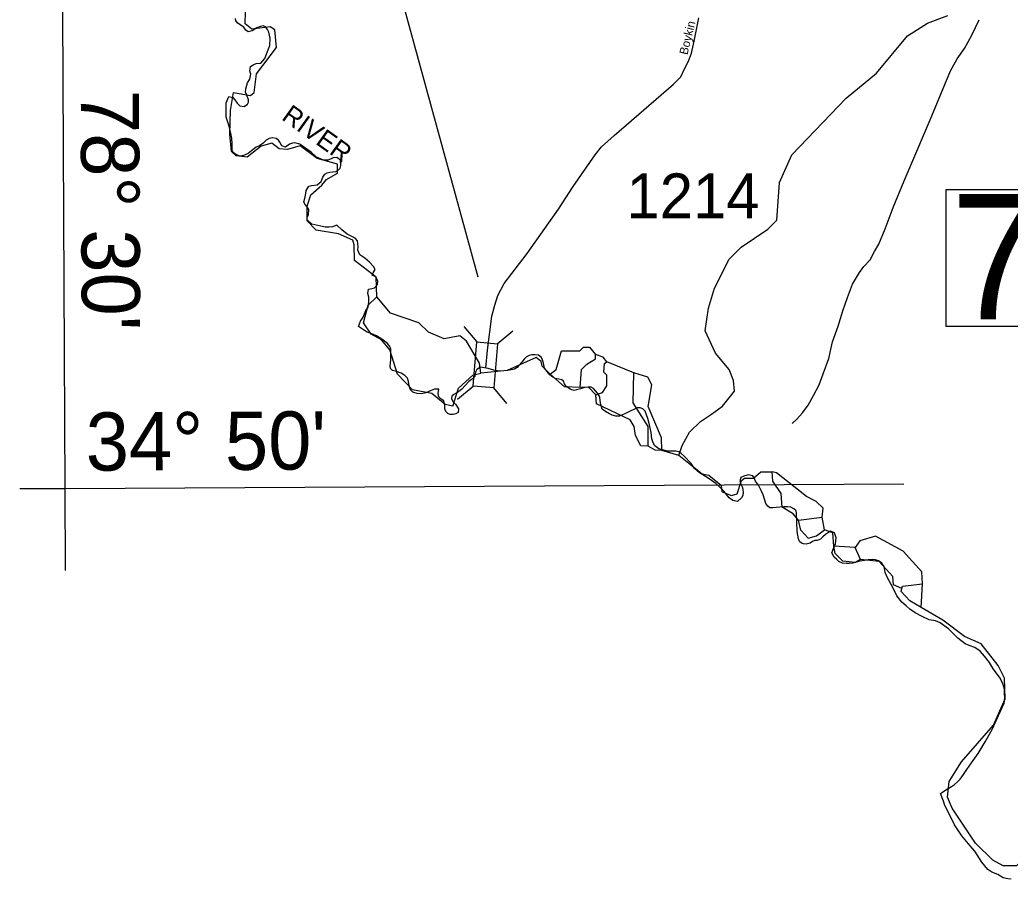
# Model space of a CAD drawing. Extents: x 2093524 to 2270757, y 289120 to 570408.
# Drawn here: x 2149570 to 2160640, y 390085 to 399685 of the extents above; entities that cross this region are included whole.
import ezdxf

# ---------------------------------------------------------------- set-up
doc = ezdxf.new("R2010")
doc.units = 0
for name, color, linetype in [('Exist Boundary Political CountyLine', 7, 'Continuous'), ('Exist Hydrographic Misc Water Feature', 7, 'Continuous'), ('Exist Hydrographic River Shore Label', 7, 'Continuous'), ('Exist Road Non-System Type 51', 7, 'Continuous'), ('Exist Road Secondary Structure Standard Bridge CELL', 7, 'Continuous'), ('Exist Road Secondary Structure Standard Bridge Number Label', 7, 'Continuous'), ('Exist Road Secondary Type 51 Attributed', 7, 'Continuous'), ('Exist Road Secondary Type 51 Label', 7, 'Continuous'), ('Exist Road Secondary Type 51 Number Label', 7, 'Continuous'), ('Map Preparation Longitude Latitude Label', 7, 'Continuous'), ('Map Preparation Longitude Latitude Lines', 7, 'Continuous')]:
    doc.layers.add(name, color=color, linetype=linetype)

msp = doc.modelspace()

# ---------------------------------------------------------------- linework, layer by layer
at = {"layer": 'Exist Boundary Political CountyLine'}
for points in [[(2153159, 398059), (2153154, 398118), (2153112, 398147), (2153074, 398143), (2153018, 398116), (2152965, 398116), (2152886, 398151), (2152826, 398205), (2152742, 398265), (2152700, 398296), (2152644, 398309), (2152616, 398308), (2152585, 398295), (2152538, 398264), (2152500, 398279), (2152476, 398320), (2152462, 398342), (2152437, 398358), (2152396, 398366), (2152358, 398358), (2152322, 398342), (2152289, 398308), (2152248, 398277), (2152210, 398261), (2152160, 398220), (2152121, 398193), (2152070, 398168), (2152032, 398163), (2151984, 398179), (2151956, 398203), (2151945, 398230), (2151943, 398303), (2151941, 398358), (2151930, 398418), (2151906, 398508), (2151876, 398598), (2151876, 398659), (2151876, 398759), (2151906, 398827), (2151952, 398816), (2151974, 398790), (2152000, 398753), (2152030, 398724), (2152076, 398716), (2152115, 398741), (2152126, 398766), (2152125, 398792), (2152106, 398843), (2152093, 398878), (2152096, 398915), (2152116, 398981), (2152141, 399021), (2152152, 399077), (2152142, 399111), (2152148, 399163), (2152184, 399184), (2152213, 399198), (2152263, 399199), (2152310, 399251), (2152328, 399300), (2152348, 399362), (2152363, 399398), (2152368, 399480), (2152354, 399546), (2152339, 399577), (2152315, 399605), (2152290, 399616), (2152260, 399611), (2152219, 399596), (2152167, 399560), (2152122, 399552), (2152095, 399570), (2152075, 399603), (2152032, 399630), (2152007, 399646), (2151986, 399673), (2151980, 399700)], [(2154420, 395500), (2154398, 395481), (2154395, 395454), (2154410, 395422), (2154441, 395390), (2154475, 395339), (2154468, 395297), (2154444, 395284), (2154415, 395277), (2154382, 395277), (2154354, 395287), (2154332, 395308), (2154319, 395341), (2154322, 395377), (2154310, 395429), (2154278, 395447), (2154254, 395472), (2154247, 395509), (2154255, 395559), (2154204, 395558), (2154166, 395546), (2154108, 395519), (2154058, 395507), (2154013, 395512), (2153961, 395524), (2153936, 395551), (2153921, 395598), (2153913, 395644), (2153903, 395681), (2153874, 395712), (2153833, 395738), (2153780, 395755), (2153734, 395767), (2153714, 395790), (2153709, 395817), (2153718, 395885), (2153718, 395967), (2153718, 396005), (2153706, 396036), (2153678, 396068), (2153618, 396118), (2153557, 396154), (2153503, 396177), (2153444, 396198), (2153355, 396259), (2153377, 396317), (2153408, 396362), (2153439, 396439), (2153463, 396474), (2153472, 396533), (2153472, 396586), (2153460, 396627), (2153468, 396675), (2153506, 396685), (2153535, 396691), (2153569, 396729), (2153571, 396767), (2153548, 396813), (2153509, 396832), (2153518, 396859), (2153543, 396896), (2153525, 396928), (2153478, 396978), (2153428, 397024), (2153372, 397058), (2153348, 397113), (2153352, 397150), (2153349, 397186), (2153343, 397215), (2153317, 397244), (2153229, 397290), (2153168, 397340), (2153112, 397390), (2153064, 397373), (2153028, 397368), (2152983, 397368), (2152933, 397380), (2152834, 397404), (2152780, 397452), (2152781, 397478), (2152795, 397509), (2152800, 397565), (2152782, 397594), (2152754, 397624), (2152746, 397653), (2152757, 397689), (2152768, 397744), (2152772, 397779), (2152799, 397828), (2152829, 397833), (2152894, 397840), (2152937, 397879), (2152956, 397929), (2152980, 397962), (2153004, 397977), (2153036, 397984), (2153101, 397990), (2153129, 398007), (2153150, 398029), (2153159, 398059)], [(2157877, 394379), (2157855, 394426), (2157828, 394487), (2157792, 394531), (2157777, 394567), (2157762, 394591), (2157710, 394603), (2157662, 394589), (2157630, 394574), (2157618, 394534), (2157630, 394499), (2157648, 394462), (2157651, 394436), (2157654, 394404), (2157650, 394373), (2157636, 394347), (2157593, 394306), (2157540, 394314), (2157497, 394347), (2157440, 394420), (2157396, 394465), (2157351, 394507), (2157254, 394571), (2157167, 394623), (2157112, 394674), (2157073, 394727), (2156995, 394810), (2156964, 394839), (2156936, 394860), (2156903, 394866), (2156846, 394866), (2156808, 394868), (2156768, 394878), (2156711, 394892), (2156667, 394926), (2156650, 394961), (2156636, 395004), (2156628, 395075), (2156605, 395177), (2156588, 395232), (2156560, 395312), (2156534, 395339), (2156503, 395351), (2156470, 395349), (2156434, 395333), (2156392, 395315), (2156340, 395288), (2156274, 395259), (2156232, 395259), (2156190, 395268), (2156163, 395283), (2156116, 395309), (2156081, 395335), (2156063, 395387), (2156058, 395430), (2156052, 395473), (2156027, 395516), (2155984, 395568), (2155956, 395581), (2155919, 395583), (2155884, 395576), (2155838, 395563), (2155794, 395550), (2155766, 395546), (2155728, 395555), (2155676, 395590), (2155658, 395620), (2155648, 395647), (2155629, 395665), (2155595, 395670), (2155552, 395678), (2155526, 395692), (2155495, 395720), (2155436, 395794), (2155422, 395848), (2155413, 395886), (2155401, 395914), (2155368, 395940), (2155327, 395943), (2155294, 395941), (2155264, 395937), (2155235, 395922), (2155206, 395895), (2155182, 395862), (2155149, 395824), (2155128, 395802), (2155098, 395781), (2155026, 395768), (2154932, 395762), (2154867, 395771), (2154806, 395790), (2154719, 395804), (2154678, 395778), (2154665, 395748), (2154657, 395703), (2154628, 395674), (2154588, 395643), (2154511, 395558), (2154474, 395528), (2154420, 395500)], [(2160562, 390102), (2160503, 390136), (2160436, 390162), (2160391, 390192), (2160323, 390277), (2160244, 390398), (2160194, 390458), (2160100, 390568), (2160019, 390693), (2159951, 390830), (2159909, 390910), (2159895, 390956), (2159860, 391042), (2159883, 391057), (2159922, 391084), (2159964, 391109), (2160014, 391140), (2160054, 391175), (2160082, 391202), (2160118, 391255), (2160157, 391309), (2160207, 391385), (2160281, 391491), (2160360, 391620), (2160439, 391758), (2160508, 391912), (2160574, 392050), (2160580, 392107), (2160578, 392159), (2160576, 392207), (2160558, 392270), (2160519, 392343), (2160450, 392434), (2160410, 392507), (2160351, 392578), (2160304, 392632), (2160246, 392673), (2160182, 392694), (2160136, 392714), (2160056, 392777), (2159949, 392883), (2159858, 392950), (2159806, 392970), (2159734, 392984), (2159656, 393018), (2159578, 393059), (2159518, 393100), (2159476, 393138), (2159430, 393180), (2159373, 393251), (2159327, 393344), (2159269, 393453), (2159241, 393512), (2159231, 393577), (2159206, 393616), (2159168, 393642), (2159133, 393653), (2159099, 393655), (2159054, 393654), (2159011, 393647), (2158959, 393638), (2158878, 393616), (2158840, 393611), (2158809, 393613), (2158765, 393616), (2158726, 393633), (2158702, 393656), (2158673, 393683), (2158648, 393730), (2158667, 393792), (2158689, 393833), (2158696, 393899), (2158678, 393954), (2158632, 393973), (2158575, 393934), (2158544, 393908), (2158518, 393885), (2158483, 393870), (2158456, 393867), (2158429, 393856), (2158403, 393840), (2158358, 393826), (2158331, 393830), (2158306, 393838), (2158286, 393857), (2158272, 393888), (2158260, 393968), (2158254, 394081), (2158250, 394173), (2158247, 394201), (2158220, 394224), (2158189, 394241), (2158150, 394244), (2158110, 394243), (2158025, 394236), (2157986, 394233), (2157954, 394234), (2157930, 394251), (2157909, 394281), (2157877, 394379)], [(2160651, 390085), (2160613, 390090), (2160562, 390102)]]:
    msp.add_lwpolyline(points, dxfattribs=at)
at = {"layer": 'Exist Hydrographic Misc Water Feature'}
for p, q in [((2152370, 399608), (2152162, 399582)), ((2151958, 398874), (2152149, 398841)), ((2152702, 398276), (2152561, 398236)), ((2156432, 395741), (2156131, 395865)), ((2155658, 395586), (2155499, 395727)), ((2155833, 395579), (2155658, 395586)), ((2155925, 395581), (2155833, 395579)), ((2156009, 395497), (2155925, 395581)), ((2156017, 395395), (2156009, 395497)), ((2156595, 394924), (2156512, 394926)), ((2156670, 394877), (2156595, 394924)), ((2156745, 394875), (2156670, 394877)), ((2156937, 394819), (2156745, 394875)), ((2157196, 394611), (2156937, 394819)), ((2157422, 394413), (2157523, 394371)), ((2158274, 394094), (2158540, 394128)), ((2158566, 393986), (2158540, 394128)), ((2158909, 393789), (2158667, 393804)), ((2158968, 393657), (2158909, 393789)), ((2158968, 393657), (2158910, 393622)), ((2159428, 393333), (2159336, 393374)), ((2159646, 393119), (2159661, 393384)), ((2159646, 393119), (2159520, 393193))]:
    msp.add_line(p, q, dxfattribs=at)
for points in [[(2152162, 399582), (2152087, 399640), (2152094, 399774), (2152375, 400142), (2152441, 400390), (2152432, 400518), (2152373, 400559)], [(2156937, 394819), (2156973, 394931), (2157056, 395079), (2157177, 395199), (2157302, 395278), (2157425, 395370), (2157558, 395538), (2157549, 395657), (2157498, 395779), (2157347, 395962), (2157229, 396211), (2157269, 396463), (2157335, 396688), (2157500, 397012), (2157632, 397147), (2157931, 397348), (2158030, 397448), (2158061, 397867), (2158201, 398176), (2158806, 398810), (2159146, 399089), (2159493, 399505), (2159717, 399648), (2159942, 399732)], [(2152149, 398841), (2152191, 398873), (2152215, 399083), (2152438, 399377), (2152420, 399574), (2152370, 399608)], [(2151919, 398406), (2151925, 398672), (2151958, 398874)], [(2152112, 398150), (2151987, 398165), (2151936, 398215), (2151919, 398406)], [(2152386, 398308), (2152269, 398274), (2152112, 398150)], [(2152561, 398236), (2152469, 398244), (2152386, 398308)], [(2153562, 396592), (2153552, 396809), (2153309, 396997), (2153308, 397171), (2153291, 397224), (2153133, 397296), (2152883, 397337), (2152782, 397438), (2152781, 397602), (2152822, 397729), (2152946, 397838), (2152996, 397902), (2153121, 397972), (2153120, 398071), (2152895, 398137), (2152702, 398276)], [(2153413, 396300), (2153462, 396499), (2153562, 396592)], [(2154724, 395739), (2154707, 395848), (2154564, 396097), (2154489, 396154), (2154314, 396121), (2154139, 396194), (2154030, 396301), (2153712, 396409), (2153562, 396592)], [(2154410, 395371), (2154326, 395386), (2154176, 395511), (2153959, 395551), (2153791, 395725), (2153706, 395999), (2153614, 396109), (2153497, 396174), (2153413, 396300)], [(2155499, 395727), (2155565, 395778), (2155623, 395987), (2155831, 395986), (2155872, 396028), (2155939, 396030), (2156006, 395946)], [(2155340, 395911), (2155016, 395766), (2154724, 395739)], [(2155499, 395727), (2155407, 395817), (2155398, 395867), (2155340, 395911)], [(2155833, 395579), (2155849, 395779), (2155907, 395837), (2156006, 395897), (2156006, 395946)], [(2156131, 395865), (2156090, 395915), (2156006, 395946)], [(2156009, 395497), (2156083, 395522), (2156133, 395596), (2156132, 395714), (2156099, 395748), (2156107, 395846), (2156131, 395865)], [(2154410, 395371), (2154475, 395570), (2154633, 395715), (2154724, 395739)], [(2156595, 394924), (2156594, 395141), (2156425, 395407), (2156432, 395741)], [(2156745, 394875), (2156744, 395017), (2156592, 395367), (2156633, 395609), (2156591, 395692), (2156432, 395741)], [(2156512, 394926), (2156453, 395042), (2156435, 395141), (2156393, 395217), (2156017, 395395)], [(2157422, 394413), (2157414, 394478), (2157271, 394596), (2157196, 394611)], [(2157523, 394371), (2157589, 394390), (2157638, 394540), (2157671, 394565), (2157772, 394566)], [(2157772, 394566), (2157854, 394634), (2157979, 394634)], [(2158540, 394128), (2158548, 394229), (2158473, 394303), (2158364, 394361), (2158029, 394624), (2157979, 394634)], [(2158274, 394094), (2158215, 394167), (2158090, 394242), (2158081, 394393), (2157988, 394533), (2157979, 394634)], [(2158383, 393895), (2158300, 393985), (2158274, 394094)], [(2158383, 393895), (2158475, 393919), (2158566, 393986)], [(2158667, 393804), (2158658, 393955), (2158566, 393986)], [(2159661, 393384), (2159652, 393519), (2159442, 393749), (2159133, 393916), (2158958, 393864), (2158909, 393789)], [(2158910, 393622), (2158768, 393638), (2158684, 393722), (2158667, 393804)], [(2159336, 393374), (2159327, 393466), (2159176, 393633), (2158968, 393657)], [(2159520, 393193), (2159420, 393300), (2159428, 393333)], [(2159428, 393333), (2159436, 393359), (2159661, 393384)], [(2160562, 390233), (2160445, 390298), (2160252, 390489), (2159991, 390878), (2159941, 391003), (2159956, 391177), (2160097, 391397), (2160453, 391807), (2160584, 392099), (2160575, 392332), (2160507, 392472), (2160314, 392715), (2160131, 392797), (2159888, 392979), (2159646, 393119)], [(2161317, 390779), (2161208, 390768), (2161009, 390710), (2160918, 390600), (2160827, 390349), (2160711, 390234), (2160562, 390233)]]:
    msp.add_lwpolyline(points, dxfattribs=at)
at = {"layer": 'Exist Road Non-System Type 51'}
msp.add_lwpolyline([(2158204, 395174), (2158254, 395224), (2158319, 395294), (2158381, 395382), (2158440, 395489), (2158503, 395607), (2158549, 395731), (2158612, 395900), (2158655, 396088), (2158718, 396262), (2158769, 396434), (2158822, 396584), (2158879, 396733), (2158954, 396861), (2159004, 396931), (2159074, 397002), (2159125, 397096), (2159170, 397178), (2159241, 397351), (2159332, 397587), (2159454, 397886), (2159596, 398218), (2159744, 398569), (2159908, 398964), (2159973, 399114), (2160048, 399248), (2160130, 399363), (2160213, 399515), (2160294, 399686)], dxfattribs=at)
at = {"layer": 'Exist Road Secondary Structure Standard Bridge CELL'}
for p, q in [((2154681, 396087), (2154536, 396260)), ((2154907, 396067), (2155080, 396212)), ((2154463, 395448), (2154636, 395593)), ((2155012, 395399), (2154867, 395573))]:
    msp.add_line(p, q, dxfattribs=at)
msp.add_lwpolyline([(2154636, 395593), (2154680, 396087), (2154911, 396066), (2154867, 395573)], close=True, dxfattribs=at)
at = {"layer": 'Exist Road Secondary Structure Standard Bridge Number Label'}
msp.add_line((2154692, 396811), (2152660, 404215), dxfattribs=at)
msp.add_lwpolyline([(2159924, 397788), (2162501, 397788), (2162501, 396259), (2159924, 396259)], close=True, dxfattribs=at)
at = {"layer": 'Exist Road Secondary Type 51 Attributed'}
msp.add_lwpolyline([(2154778, 395795), (2154796, 395993), (2154846, 396375), (2154880, 396496), (2154914, 396606), (2154984, 396740), (2155242, 397076), (2155590, 397568), (2155756, 397823), (2156002, 398178), (2156073, 398266), (2156215, 398393), (2156877, 398965), (2156959, 399049), (2157000, 399139), (2157045, 399223), (2157079, 399312), (2157107, 399446), (2157160, 399707)], dxfattribs=at)
at = {"layer": 'Map Preparation Longitude Latitude Lines'}
for points in [[(2150082, 393535), (2150077, 394450), (2150016, 406612)], [(2149570, 394448), (2150077, 394450), (2159452, 394501)]]:
    msp.add_lwpolyline(points, dxfattribs=at)

# ---------------------------------------------------------------- texts
at = {"layer": 'Exist Hydrographic River Shore Label'}
msp.add_text('RIVER', height=210, rotation=324.3988, dxfattribs=at).set_placement((2152485, 398578))
at = {"layer": 'Exist Road Secondary Structure Standard Bridge Number Label'}
msp.add_text('77', height=1400, dxfattribs=at).set_placement((2159975, 396338))
at = {"layer": 'Exist Road Secondary Type 51 Label'}
msp.add_text('Boykin', height=95, rotation=76.2843, dxfattribs=at).set_placement((2157032, 399288))
at = {"layer": 'Exist Road Secondary Type 51 Number Label'}
msp.add_text('1214', height=500, dxfattribs=at).set_placement((2156351, 397469))
at = {"layer": 'Map Preparation Longitude Latitude Label'}
for s, rotation, p in [("78° 30'", 270.2886, (2150251, 398900)), ("34° 50'", 0.3126, (2150308, 394648))]:
    msp.add_text(s, height=650, rotation=rotation, dxfattribs=at).set_placement(p)

doc.saveas('drawing.dxf')
